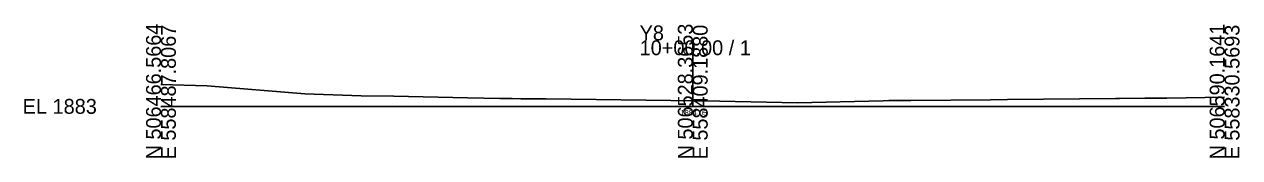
# Model space of a CAD drawing. Extents: x -26 to 203, y -10 to 8070.
# Drawn here: x -25.7 to 202.8, y -9.7 to 15.5 of the extents above; entities that cross this region are included whole.
import ezdxf

# ---------------------------------------------------------------- set-up
doc = ezdxf.new("R2010")
doc.units = 0
for name, color, linetype in [('Default', 7, 'Continuous'), ('Exist Cross Section Cell', 7, 'Continuous'), ('Exist XS Center Line Elevation Label', 7, 'Continuous'), ('Exist XS Ground Line', 7, 'Continuous')]:
    doc.layers.add(name, color=color, linetype=linetype)

msp = doc.modelspace()

# ---------------------------------------------------------------- linework, layer by layer
at = {"layer": 'Exist Cross Section Cell'}
for p, q in [((100, 0), (100, 12.46)), ((0, 0), (100, 0)), ((100, 0), (200, 0))]:
    msp.add_line(p, q, dxfattribs=at)
at = {"layer": 'Exist XS Ground Line'}
for p, q in [((0, 4.15), (8.68, 3.89)), ((8.68, 3.89), (27.07, 2.38)), ((27.07, 2.38), (37.67, 2.01)), ((37.67, 2.01), (43.8, 1.91)), ((43.8, 1.91), (57.63, 1.59)), ((57.63, 1.59), (63.72, 1.49)), ((63.72, 1.49), (66.05, 1.47)), ((66.05, 1.47), (67.64, 1.43)), ((67.64, 1.43), (69.97, 1.41)), ((69.97, 1.41), (71.34, 1.41)), ((71.34, 1.41), (72.43, 1.4)), ((72.43, 1.4), (100.59, 1.04)), ((100.59, 1.04), (101.25, 1.04)), ((101.25, 1.04), (101.56, 1.03)), ((101.56, 1.03), (102.12, 1.02)), ((102.12, 1.02), (119.67, 0.69)), ((119.67, 0.69), (135.82, 1.07)), ((135.82, 1.07), (136.86, 1.09)), ((136.86, 1.09), (141, 1.13)), ((141, 1.13), (156.01, 1.24)), ((156.01, 1.24), (159.17, 1.27)), ((159.17, 1.27), (179.5, 1.46)), ((179.5, 1.46), (180.26, 1.46)), ((180.26, 1.46), (185.03, 1.53)), ((185.03, 1.53), (189.17, 1.58)), ((189.17, 1.58), (200, 1.73))]:
    msp.add_line(p, q, dxfattribs=at)

# ---------------------------------------------------------------- texts
at = {"layer": 'Default'}
msp.add_text('-', height=0.0001, dxfattribs=at).set_placement((0, 0))
at = {"layer": 'Exist Cross Section Cell'}
for s, p in [('N 506466.5664', (0, -10)), ('E 558487.8067', (2.8, -10)), ('N 506528.3653', (100, -10)), ('E 558409.1880', (102.8, -10)), ('N 506590.1641', (200, -10)), ('E 558330.5693', (202.8, -10))]:
    msp.add_text(s, height=2.8, rotation=90, dxfattribs=at).set_placement(p)
for s, p in [('Y8', (90, 12.46)), ('10+00.00 / 1', (90, 9.66)), ('EL 1883', (-26, -1.4))]:
    msp.add_text(s, height=2.8, dxfattribs=at).set_placement(p)
at = {"layer": 'Exist XS Center Line Elevation Label'}
msp.add_text('1884.05', height=1, dxfattribs=at).set_placement((97.7, -1.7))

doc.saveas('drawing.dxf')
